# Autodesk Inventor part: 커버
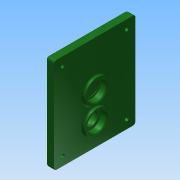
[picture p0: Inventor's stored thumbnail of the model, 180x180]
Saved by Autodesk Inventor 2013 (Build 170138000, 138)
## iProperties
Created: 2016-02
Part Number: 커버
Material: 알루미늄 6061
Document SubType Name: Modeling
Designer: mduedu
Density: 2.71 g/cm^3
Mass: 272.253 g
Surface Area: 266.629 cm^2
Volume: 100.462 cm^3
Author: mduedu
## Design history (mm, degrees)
sketch "스케치1"
  geometry: L1 (63, 47)-(-47, 47); L2 (-47, 47)-(-47, -47); L3 (-47, -47)-(63, -47); L4 (63, -47)-(63, 47); 2 further points
  constraints: 8 end point, 2 parallel, 1 horizontal, 1 horizontal alignment, 1 midpoint, 1 perpendicular
  dimensions: "d102" = 94 distance of L3.end L1.start; "d104" = 47 distance from line of L2 point (0, 0); "d105" = 110 distance of L1.start L1.end
extrude "돌출1" new body sketch "스케치1" distance "d1" = 10; taper "d2" = 0 deg
sketch "스케치2"
  geometry: C1 r 14 at (0, 11); 1 further point
  constraints: 1 centre point, 1 vertical alignment
  dimensions: "d3" = 28 diameter of C1; "d6" = 11 distance of C1.centre point (0, 0)
extrude "돌출2" join sketch "스케치2" distance "d7" = 3; taper "d8" = 0 deg
sketch "스케치3"
  geometry: C1 r 14 at (0, -20); 1 further point
  constraints: 1 centre point, 1 vertical alignment
  dimensions: "d9" = 28 diameter of C1; "d10" = 20 distance of C1.centre point (0, 0)
extrude "돌출3" join sketch "스케치3" distance "d11" = 3; taper "d12" = 0 deg
hole "구멍1" diameter "d15" = 22; stored, may be unused: countersink angle "d19" = 90 deg, drill point angle "d21" = 0 deg; dims "d13" = 10, "d14" = 10, "d16" = 6, "d17" = 4, "d18" = 2, "d20" = 7
hole "구멍2" diameter "d24" = 18; stored, may be unused: countersink angle "d28" = 90 deg, drill point angle "d30" = 0 deg; dims "d22" = 10, "d23" = 10, "d25" = 6, "d26" = 4, "d27" = 2, "d29" = 1
hole "구멍3" diameter "d33" = 22; stored, may be unused: countersink angle "d37" = 90 deg, drill point angle "d39" = 0 deg; dims "d34" = 6, "d35" = 4, "d36" = 2, "d38" = 7, "d73" = 10, "d74" = 10
sketch "스케치4"
  geometry: C1 r 14 at (0, -20) reference; C2 r 18 at (0, -20); 1 further point
  constraints: 1 centre point, 1 coincident
  dimensions: "d40" = 36 diameter of C2
extrude "돌출4" join sketch "스케치4" distance "d41" = 4; taper "d42" = 0 deg
hole "구멍4" diameter "d45" = 22; stored, may be unused: countersink angle "d49" = 90 deg, drill point angle "d51" = 0 deg; dims "d43" = 10, "d44" = 10, "d46" = 6, "d47" = 4, "d48" = 2, "d50" = 7
hole "구멍5" diameter "d54" = 15; stored, may be unused: countersink angle "d58" = 90 deg, drill point angle "d60" = 0 deg; dims "d52" = 10, "d53" = 10, "d55" = 6, "d56" = 4, "d57" = 2, "d59" = 7
fillet "모깎기1" dims "d61" = 0.3
fillet "모깎기2" dims "d62" = 2
chamfer "모따기1" distance "d63" = 1; stored, may be unused: second distance "d64" = 2, angle "d65" = 45 deg
fillet "모깎기6" dims "d88" = 2
fillet "모깎기4" dims "d75" = 2
sketch "스케치9"
  geometry: L1 (47, 63)-(47, -47) reference; L2 (-47, 63)-(47, 63) reference; L3 (-47, -47)-(-47, 63) reference; L4 (47, -47)-(-47, -47) reference; L5 (37, 53)-(37, -37); L6 (37, -37)-(-37, -37); L7 (-37, -37)-(-37, 53); L8 (-37, 53)-(37, 53); C1 r 20 at (0, -20) reference; 5 further points
  constraints: 8 end point, 4 coincident, 3 other
  dimensions: "d107" = 10 distance between parallel lines of L8 L2
hole "구멍7" sketch "스케치9" at (-37, 53), (37, 53), (37, -37), (-37, -37) diameter "d108" = 4.5; stored, may be unused: countersink angle "d112" = 90 deg, drill point angle "d114" = 118 deg; dims "d109" = 6, "d110" = 8, "d111" = 4.6, "d113" = 8
fillet "모깎기8" dims "d106" = 3
fillet "모깎기9" dims "d115" = 3
node "솔리드1"
node "투영된 루프2"
